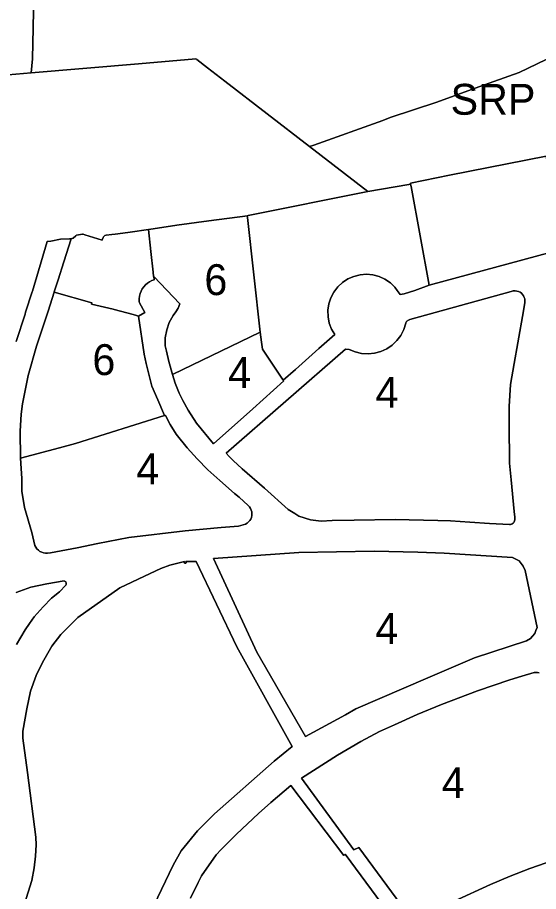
# Model space of a CAD drawing. Extents: x 598968 to 613553, y 4409678 to 4430833.
# Drawn here: x 600050.4 to 600253, y 4411856.8 to 4412196.6 of the extents above; entities that cross this region are included whole.
import ezdxf

# ---------------------------------------------------------------- set-up
doc = ezdxf.new("R2010")
doc.units = 0
for name, color, linetype in [('1', 7, 'Continuous'), ('Sòl Rústic Protegit', 7, 'Continuous'), ('Sòl Rústic Protegit - Alt Nivell de Protecció', 7, 'Continuous'), ('ZONA 4. CASES UNIFAMILIRAS AÏLLADES EN PARCEL.LES', 7, 'Continuous'), ('ZONA 6. EDIFICIS DE PISOS_ AÏLLATS I EN PARCEL.LES', 7, 'Continuous')]:
    doc.layers.add(name, color=color, linetype=linetype)

msp = doc.modelspace()

# ---------------------------------------------------------------- linework, layer by layer
at = {"layer": '1'}
for points in [[(600049.8615, 4412070.618), (600053.3133, 4412081.2583), (600053.5626, 4412082.0269), (600056.1294, 4412089.9391), (600056.2215, 4412090.2229), (600061.9315, 4412109.4578), (600063.2902, 4412109.7029), (600067.1415, 4412110.3979), (600070.5914, 4412110.4879), (600070.8652, 4412110.5224), (600071.2192, 4412110.583), (600071.4814, 4412110.6279), (600071.6514, 4412110.6779), (600071.9914, 4412110.7979), (600073.0314, 4412111.7679), (600073.3714, 4412111.9279), (600075.7014, 4412112.3879), (600075.9752, 4412112.2999), (600076.5414, 4412112.1179), (600083.2509, 4412110.0725), (600083.3313, 4412110.048), (600083.3423, 4412110.0774), (600083.3571, 4412110.1172), (600083.7027, 4412111.0448), (600083.7113, 4412111.068), (600083.8813, 4412111.358), (600084.1013, 4412111.618), (600084.3913, 4412111.808), (600084.8512, 4412111.938), (600087.0881, 4412112.2332), (600088.3143, 4412112.3949), (600091.3819, 4412112.7996), (600094.1674, 4412113.167), (600101.3929, 4412114.1197), (600101.4317, 4412114.1254), (600101.4381, 4412114.1263), (600112.2909, 4412115.9083), (600124.8032, 4412117.561), (600139.8025, 4412119.5439), (600140.1406, 4412119.5886), (600186.6101, 4412128.919), (600163.972, 4412146.4208), (600131.0638, 4412171.8626), (600124.3198, 4412177.0765), (600120.1257, 4412180.2714), (600119.9641, 4412180.3945), (600119.8028, 4412180.5173), (600097.4846, 4412178.6181), (600055.7347, 4412175.0653), (600046.7796, 4412174.3032)], [(600262.7291, 4412106.6801), (600210.4311, 4412092.5694), (600210.4227, 4412092.5669), (600204.9248, 4412090.4696), (600200.7461, 4412089.209), (600199.2349, 4412088.8495), (600198.0504, 4412090.4502), (600197.1842, 4412091.6995), (600195.3745, 4412093.4355), (600193.2995, 4412094.8438), (600191.018, 4412095.8844), (600188.5942, 4412096.5279), (600186.0969, 4412096.7562), (600183.5967, 4412096.5628), (600181.1642, 4412095.953), (600178.8682, 4412094.9443), (600176.7738, 4412093.5651), (600174.9402, 4412091.8544), (600173.4191, 4412089.8606), (600172.2537, 4412087.6401), (600171.4768, 4412085.2558), (600171.1105, 4412082.7749), (600171.1652, 4412080.2678), (600171.6392, 4412077.8052), (600172.519, 4412075.4569), (600173.7801, 4412073.2894), (600167.6182, 4412067.8515), (600158.4369, 4412059.7489), (600153.7424, 4412055.606), (600153.9602, 4412055.2793), (600141.8561, 4412044.4851), (600126.6705, 4412030.8492), (600120.0006, 4412038.919), (600116.7406, 4412043.879), (600114.6507, 4412047.6389), (600113.2907, 4412050.5589), (600111.7407, 4412054.3788), (600110.6158, 4412057.7946), (600109.2708, 4412062.8287), (600108.3108, 4412066.8687), (600107.8208, 4412068.9787), (600107.8776, 4412072.0645), (600108.4192, 4412075.1031), (600109.432, 4412078.0187), (600110.8908, 4412080.7386), (600111.9807, 4412082.1192), (600112.8792, 4412083.6313), (600113.5708, 4412085.2486), (600103.3456, 4412095.915), (600103.4795, 4412094.6664), (600102.681, 4412094.3384), (600101.771, 4412093.8884), (600100.921, 4412093.3284), (600100.161, 4412092.6684), (600099.471, 4412091.9184), (600098.891, 4412091.0784), (600098.421, 4412090.1884), (600098.061, 4412089.2384), (600097.821, 4412088.2484), (600097.721, 4412087.2384), (600097.731, 4412086.2184), (600097.891, 4412085.6484), (600099.9054, 4412081.8442), (600097.4411, 4412080.4786), (600099.6004, 4412065.6697), (600100.4364, 4412062.0667), (600102.6109, 4412053.2334), (600105.0151, 4412047.9689), (600107.5508, 4412041.869), (600107.5937, 4412041.8106), (600107.8806, 4412041.901), (600109.7807, 4412038.3089), (600112.1486, 4412034.5515), (600116.3973, 4412029.2343), (600120.2029, 4412025.0051), (600124.4505, 4412020.7192), (600129.0504, 4412016.6293), (600134.8353, 4412011.5098), (600136.5553, 4412010.0544), (600140.0902, 4412006.8145), (600140.5901, 4412006.3014), (600140.9979, 4412005.7124), (600141.3023, 4412005.0639), (600141.4948, 4412004.3738), (600141.5701, 4412003.6614), (600141.5261, 4412002.9464), (600141.3641, 4412002.2485), (600141.0884, 4412001.5873), (600140.7068, 4412000.981), (600140.2299, 4412000.4464), (600139.6709, 4411999.9985), (600139.0452, 4411999.6495), (600136.3152, 4411998.8795), (600129.5503, 4411998.3194), (600115.5713, 4411997.0609), (600093.662, 4411994.3632), (600081.6435, 4411992.0302), (600073.548, 4411990.4186), (600063.2401, 4411988.4464), (600062.053, 4411988.366), (600061.2904, 4411988.3438), (600060.5342, 4411988.4448), (600059.8041, 4411988.6665), (600059.1194, 4411989.0029), (600058.4978, 4411989.4453), (600057.9556, 4411989.9821), (600057.5071, 4411990.5992), (600057.1639, 4411991.2806), (600055.9069, 4411996.3742), (600053.0813, 4412006.1185), (600052.0613, 4412012.4485), (600052.0913, 4412017.3084), (600051.8414, 4412021.2934), (600051.5915, 4412025.2785), (600051.4391, 4412035.7522), (600051.7813, 4412042.3955), (600052.2839, 4412046.3341), (600054.4999, 4412057.3549), (600057.8123, 4412068.7686), (600062.2693, 4412082.46), (600064.6883, 4412089.8585), (600064.7053, 4412089.9109), (600066.1656, 4412094.5453), (600068.391, 4412101.6077), (600071.2192, 4412110.583), (600070.8652, 4412110.5224), (600070.5914, 4412110.4879), (600067.1415, 4412110.3979), (600063.2902, 4412109.7029), (600061.9315, 4412109.4578), (600056.2215, 4412090.2229), (600056.1294, 4412089.9391), (600053.5626, 4412082.0269), (600053.3133, 4412081.2583), (600049.8615, 4412070.618)], [(600047.3083, 4411833.433), (600055.9112, 4411861.0664), (600056.8748, 4411865.9952), (600057.4139, 4411870.4996), (600057.6244, 4411874.8692), (600057.551, 4411877.8432), (600054.2469, 4411903.0482), (600052.4267, 4411916.4206), (600052.4933, 4411919.0858), (600054.0587, 4411927.8213), (600055.4528, 4411934.6005), (600057.661, 4411940.7246), (600060.0778, 4411945.8539), (600063.7094, 4411952.1345), (600067.3009, 4411956.689), (600073.9111, 4411963.2891), (600090.1407, 4411974.8292), (600101.9189, 4411980.3707), (600106.1348, 4411982.4116), (600109.6232, 4411983.6618), (600115.3405, 4411985.0294), (600115.3, 4411984.9768), (600115.269, 4411984.9181), (600115.2483, 4411984.855), (600115.2386, 4411984.7893), (600115.2401, 4411984.7229), (600115.2529, 4411984.6577), (600115.2765, 4411984.5956), (600115.3102, 4411984.5384), (600115.3531, 4411984.4878), (600115.404, 4411984.4451), (600115.4613, 4411984.4116), (600115.5235, 4411984.3883), (600115.5886, 4411984.3758), (600115.655, 4411984.3746), (600115.7207, 4411984.3846), (600115.7837, 4411984.4055), (600115.8423, 4411984.4368), (600115.8947, 4411984.4776), (600115.9395, 4411984.5266), (600115.9754, 4411984.5825), (600116.0013, 4411984.6436), (600116.0164, 4411984.7083), (600116.0205, 4411984.7746), (600116.0133, 4411984.8406), (600115.995, 4411984.9044), (600115.9662, 4411984.9643), (600115.9277, 4411985.0184), (600115.8806, 4411985.0652), (600119.9262, 4411985.1364), (600135.6651, 4411951.8536), (600157.2382, 4411913.1078), (600150.2627, 4411907.4293), (600126.9553, 4411886.9084), (600120.4289, 4411880.3218), (600114.0378, 4411872.5894), (600110.8813, 4411867.0087), (600103.4226, 4411851.2731)], [(600049.9164, 4411973.087), (600055.5817, 4411975.1205), (600061.7464, 4411976.4456), (600068.5541, 4411977.5326), (600068.7222, 4411977.4667), (600069.1592, 4411977.1819), (600069.2996, 4411976.6876), (600069.343, 4411976.4457), (600069.3095, 4411976.147), (600069.1882, 4411975.8372), (600066.6782, 4411973.3356), (600063.6342, 4411970.7754), (600060.4189, 4411967.4243), (600056.917, 4411963.5264), (600055.1112, 4411960.9603), (600053.3454, 4411958.4509), (600049.9554, 4411952.8451)], [(600204.9496, 4411844.2805), (600183.1431, 4411873.8948), (600181.2357, 4411872.9034), (600160.801, 4411900.8292), (600174.8031, 4411909.794), (600183.9284, 4411915.0814), (600191.2021, 4411918.9549), (600196.9393, 4411921.5919), (600205.8249, 4411925.5367), (600215.2392, 4411929.4402), (600229.2993, 4411934.7638), (600241.8117, 4411939.1135), (600246.5122, 4411940.513), (600251.3232, 4411941.8849), (600252.632, 4411941.8984), (600253.1968, 4411941.7776)], [(600117.7267, 4411854.1749), (600120.7046, 4411860.3242), (600121.9615, 4411862.8214), (600127.6143, 4411870.9573), (600129.5983, 4411873.153), (600135.5, 4411879.1189), (600144.1398, 4411887.0586), (600148.9525, 4411891.3378), (600156.7362, 4411898.0025), (600177.3163, 4411870.736), (600177.7522, 4411871.2171), (600200.1233, 4411841.0695)], [(600255.9473, 4411867.8648), (600249.6677, 4411865.7518), (600241.9879, 4411862.79), (600234.2846, 4411859.4223), (600220.2119, 4411852.9536)]]:
    msp.add_lwpolyline(points, dxfattribs=at)
for points in [[(600262.813, 4412106.7175), (600261.0076, 4412116.2647), (600258.611, 4412128.9381), (600255.9993, 4412142.7497), (600218.3736, 4412135.2512), (600203.2099, 4412132.2292), (600203.2723, 4412131.8236), (600203.4318, 4412130.9483), (600210.4227, 4412092.5669), (600210.4311, 4412092.5694), (600262.7291, 4412106.6801)], [(600210.4227, 4412092.5669), (600203.4318, 4412130.9483), (600203.2723, 4412131.8236), (600202.5975, 4412131.6822), (600186.6101, 4412128.919), (600140.1406, 4412119.5886), (600139.8025, 4412119.5439), (600139.7635, 4412119.5361), (600139.8337, 4412118.8952), (600144.7204, 4412074.279), (600145.2821, 4412070.4293), (600145.2979, 4412070.3208), (600145.6803, 4412067.6991), (600153.7424, 4412055.606), (600158.4369, 4412059.7489), (600167.6182, 4412067.8515), (600173.7801, 4412073.2894), (600172.519, 4412075.4569), (600171.6392, 4412077.8052), (600171.1652, 4412080.2678), (600171.1105, 4412082.7749), (600171.4768, 4412085.2558), (600172.2537, 4412087.6401), (600173.4191, 4412089.8606), (600174.9402, 4412091.8544), (600176.7738, 4412093.5651), (600178.8682, 4412094.9443), (600181.1642, 4412095.953), (600183.5967, 4412096.5628), (600186.0969, 4412096.7562), (600188.5942, 4412096.5279), (600191.018, 4412095.8844), (600193.2995, 4412094.8438), (600195.3745, 4412093.4355), (600197.1842, 4412091.6995), (600198.0504, 4412090.4502), (600199.2349, 4412088.8495), (600200.7461, 4412089.209), (600204.9248, 4412090.4696)], [(600103.3456, 4412095.915), (600103.3402, 4412095.9206), (600103.1605, 4412097.6405), (600102.3004, 4412105.6587), (600101.3929, 4412114.1197), (600094.1674, 4412113.167), (600091.3819, 4412112.7996), (600088.3143, 4412112.3949), (600087.0881, 4412112.2332), (600084.8512, 4412111.938), (600084.3913, 4412111.808), (600084.1013, 4412111.618), (600083.8813, 4412111.358), (600083.7113, 4412111.068), (600083.7027, 4412111.0448), (600083.3571, 4412110.1172), (600083.3423, 4412110.0774), (600083.3313, 4412110.048), (600083.2509, 4412110.0725), (600076.5414, 4412112.1179), (600075.9752, 4412112.2999), (600075.7014, 4412112.3879), (600073.3714, 4412111.9279), (600073.0314, 4412111.7679), (600071.9914, 4412110.7979), (600071.6514, 4412110.6779), (600071.4814, 4412110.6279), (600071.2192, 4412110.583), (600068.391, 4412101.6077), (600066.1656, 4412094.5453), (600064.7053, 4412089.9109), (600064.6883, 4412089.8585), (600079.2813, 4412085.6283), (600079.1424, 4412085.148), (600087.6368, 4412083.1658), (600087.9808, 4412083.087), (600095.381, 4412081.1184), (600096.7261, 4412080.7006), (600097.4411, 4412080.4786), (600099.9054, 4412081.8442), (600097.891, 4412085.6484), (600097.731, 4412086.2184), (600097.721, 4412087.2384), (600097.821, 4412088.2484), (600098.061, 4412089.2384), (600098.421, 4412090.1884), (600098.891, 4412091.0784), (600099.471, 4412091.9184), (600100.161, 4412092.6684), (600100.921, 4412093.3284), (600101.771, 4412093.8884), (600102.681, 4412094.3384), (600103.4795, 4412094.6664)], [(600244.9758, 4412070.1494), (600243.5159, 4412062.0412), (600242.1185, 4412053.9679), (600241.6212, 4412045.3277), (600241.545, 4412038.542), (600241.6966, 4412023.3073), (600242.3081, 4412016.8157), (600243.4964, 4412004.5704), (600243.7503, 4412002.3635), (600243.8313, 4412002.0002), (600243.852, 4412001.6286), (600243.8119, 4412001.2585), (600243.7121, 4412000.8999), (600243.5553, 4412000.5623), (600243.3456, 4412000.2548), (600243.0886, 4411999.9855), (600242.7912, 4411999.7617), (600242.4613, 4411999.5892), (600242.1079, 4411999.4728), (600241.7401, 4411999.4155), (600233.9708, 4411999.8974), (600226.3029, 4412000.3793), (600218.8346, 4412000.8904), (600213.817, 4412001.0736), (600202.733, 4412001.3225), (600197.2228, 4412001.4189), (600181.2848, 4412001.18), (600172.7849, 4412000.9895), (600168.5409, 4412000.7516), (600164.3275, 4412001.3443), (600159.82, 4412002.6997), (600158.24, 4412003.7147), (600155.6895, 4412005.3047), (600146.4368, 4412013.6436), (600137.8203, 4412021.1694), (600134.2704, 4412024.3493), (600132.7354, 4412025.9193), (600131.4905, 4412027.1899), (600177.9876, 4412067.6722), (600179.3653, 4412067.5442), (600181.7067, 4412066.5613), (600184.1783, 4412065.9784), (600186.7121, 4412065.8116), (600189.2388, 4412066.0653), (600191.6889, 4412066.7325), (600193.9954, 4412067.795), (600196.0947, 4412069.2236), (600197.9295, 4412070.9793), (600199.4493, 4412073.0136), (600200.6125, 4412075.2709), (600201.3871, 4412077.6892), (600201.4467, 4412077.9257), (600201.5409, 4412078.1507), (600201.6676, 4412078.359), (600201.8241, 4412078.5461), (600202.0067, 4412078.7078), (600202.2115, 4412078.8403), (600202.4337, 4412078.9407), (600202.9729, 4412079.1626), (600242.3305, 4412090.1182), (600243.1873, 4412090.3243), (600243.9516, 4412090.3499), (600244.5995, 4412090.2538), (600245.2235, 4412090.0547), (600245.8073, 4412089.7577), (600246.3357, 4412089.3707), (600246.7948, 4412088.9036), (600247.1727, 4412088.3686), (600247.4595, 4412087.7797), (600247.6478, 4412087.1524), (600247.7326, 4412086.5029), (600247.7117, 4412085.8482), (600247.1272, 4412082.6035)], [(600177.9809, 4411925.4922), (600162.393, 4411917.0669), (600143.5, 4411949.78), (600126.6408, 4411986.2572), (600159.8396, 4411988.5233), (600189.0775, 4411989.0617), (600206.0775, 4411988.7351), (600216.3666, 4411988.2735), (600242.919, 4411986.6508), (600245.5237, 4411985.3732), (600247.0589, 4411983.2859), (600247.7746, 4411981.6265), (600252.4892, 4411959.4202), (600251.9923, 4411958.2657), (600251.5946, 4411957.0455), (600250.7141, 4411956.0522), (600249.8903, 4411955.1441), (600248.3849, 4411954.2076), (600228.1391, 4411947.5709), (600209.9881, 4411939.9071), (600181.8936, 4411927.7553)]]:
    msp.add_lwpolyline(points, close=True, dxfattribs=at)
at = {"layer": 'Sòl Rústic Protegit'}
msp.add_lwpolyline([(600264.2805, 4412144.3996), (600264.4423, 4412146.2714), (600264.4469, 4412146.2918), (600264.6143, 4412147.0262), (600264.6151, 4412147.0298), (600273.6467, 4412188.6296), (600273.3737, 4412188.498), (600273.4139, 4412188.6828), (600245.4135, 4412175.1828), (600229.8511, 4412169.6828), (600213.4131, 4412163.6828), (600195.3505, 4412157.6828), (600192.4319, 4412156.5056), (600165.6077, 4412146.9482), (600165.5897, 4412146.9418), (600163.972, 4412146.4208), (600186.6101, 4412128.919), (600202.5975, 4412131.6822), (600203.2723, 4412131.8236), (600203.2099, 4412132.2292), (600218.3736, 4412135.2512), (600255.9993, 4412142.7497), (600256.7779, 4412142.9048)], close=True, dxfattribs=at)
at = {"layer": 'Sòl Rústic Protegit - Alt Nivell de Protecció'}
for points in [[(600046.7796, 4412174.3032), (600055.7347, 4412175.0653), (600056.1801, 4412180.5098), (600056.4593, 4412192.5632), (600056.4911, 4412193.9802), (600056.4921, 4412194.01), (600056.7901, 4412201.6602)], [(600056.7901, 4412201.6602), (600056.4921, 4412194.01), (600056.4911, 4412193.9802), (600056.4593, 4412192.5632), (600056.1801, 4412180.5098), (600055.7347, 4412175.0653), (600097.4846, 4412178.6181), (600119.8028, 4412180.5173), (600119.9641, 4412180.3945), (600120.1257, 4412180.2714), (600124.3198, 4412177.0765), (600131.0638, 4412171.8626), (600163.972, 4412146.4208), (600165.5897, 4412146.9418), (600165.6077, 4412146.9482), (600192.4319, 4412156.5056), (600195.3505, 4412157.6828), (600213.4131, 4412163.6828), (600229.8511, 4412169.6828), (600245.4135, 4412175.1828), (600273.4139, 4412188.6828)]]:
    msp.add_lwpolyline(points, dxfattribs=at)
at = {"layer": 'ZONA 4. CASES UNIFAMILIRAS AÏLLADES EN PARCEL.LES'}
for points in [[(600244.9758, 4412070.1494), (600247.1272, 4412082.6035), (600247.7117, 4412085.8482), (600247.7326, 4412086.5029), (600247.6478, 4412087.1524), (600247.4595, 4412087.7797), (600247.1727, 4412088.3686), (600246.7948, 4412088.9036), (600246.3357, 4412089.3707), (600245.8073, 4412089.7577), (600245.2235, 4412090.0547), (600244.5995, 4412090.2538), (600243.9516, 4412090.3499), (600243.1873, 4412090.3243), (600242.3305, 4412090.1182), (600202.9729, 4412079.1626), (600202.4337, 4412078.9407), (600202.2115, 4412078.8403), (600202.0067, 4412078.7078), (600201.8241, 4412078.5461), (600201.6676, 4412078.359), (600201.5409, 4412078.1507), (600201.4467, 4412077.9257), (600201.3871, 4412077.6892), (600200.6125, 4412075.2709), (600199.4493, 4412073.0136), (600197.9295, 4412070.9793), (600196.0947, 4412069.2236), (600193.9954, 4412067.795), (600191.6889, 4412066.7325), (600189.2388, 4412066.0653), (600186.7121, 4412065.8116), (600184.1783, 4412065.9784), (600181.7067, 4412066.5613), (600179.3653, 4412067.5442), (600177.9876, 4412067.6722), (600131.4905, 4412027.1899), (600132.7354, 4412025.9193), (600134.2704, 4412024.3493), (600137.8203, 4412021.1694), (600146.4368, 4412013.6436), (600155.6895, 4412005.3047), (600158.24, 4412003.7147), (600159.82, 4412002.6997), (600164.3275, 4412001.3443), (600168.5409, 4412000.7516), (600172.7849, 4412000.9895), (600181.2848, 4412001.18), (600197.2228, 4412001.4189), (600202.733, 4412001.3225), (600213.817, 4412001.0736), (600218.8346, 4412000.8904), (600226.3029, 4412000.3793), (600233.9708, 4411999.8974), (600241.7401, 4411999.4155), (600242.1079, 4411999.4728), (600242.4613, 4411999.5892), (600242.7912, 4411999.7617), (600243.0886, 4411999.9855), (600243.3456, 4412000.2548), (600243.5553, 4412000.5623), (600243.7121, 4412000.8999), (600243.8119, 4412001.2585), (600243.852, 4412001.6286), (600243.8313, 4412002.0002), (600243.7503, 4412002.3635), (600243.4964, 4412004.5704), (600242.3081, 4412016.8157), (600241.6966, 4412023.3073), (600241.545, 4412038.542), (600241.6212, 4412045.3277), (600242.1185, 4412053.9679), (600243.5159, 4412062.0412)], [(600153.7424, 4412055.606), (600145.6803, 4412067.6991), (600145.2979, 4412070.3208), (600145.2821, 4412070.4293), (600144.7204, 4412074.279), (600110.6158, 4412057.7946), (600111.7407, 4412054.3788), (600113.2907, 4412050.5589), (600114.6507, 4412047.6389), (600116.7406, 4412043.879), (600120.0006, 4412038.919), (600126.6705, 4412030.8492), (600141.8561, 4412044.4851), (600153.9602, 4412055.2793)], [(600051.5915, 4412025.2785), (600051.8414, 4412021.2934), (600052.0913, 4412017.3084), (600052.0613, 4412012.4485), (600053.0813, 4412006.1185), (600055.9069, 4411996.3742), (600057.1639, 4411991.2806), (600057.5071, 4411990.5992), (600057.9556, 4411989.9821), (600058.4978, 4411989.4453), (600059.1194, 4411989.0029), (600059.8041, 4411988.6665), (600060.5342, 4411988.4448), (600061.2904, 4411988.3438), (600062.053, 4411988.366), (600063.2401, 4411988.4464), (600073.548, 4411990.4186), (600081.6435, 4411992.0302), (600093.662, 4411994.3632), (600115.5713, 4411997.0609), (600129.5503, 4411998.3194), (600136.3152, 4411998.8795), (600139.0452, 4411999.6495), (600139.6709, 4411999.9985), (600140.2299, 4412000.4464), (600140.7068, 4412000.981), (600141.0884, 4412001.5873), (600141.3641, 4412002.2485), (600141.5261, 4412002.9464), (600141.5701, 4412003.6614), (600141.4948, 4412004.3738), (600141.3023, 4412005.0639), (600140.9979, 4412005.7124), (600140.5901, 4412006.3014), (600140.0902, 4412006.8145), (600136.5553, 4412010.0544), (600134.8353, 4412011.5098), (600129.0504, 4412016.6293), (600124.4505, 4412020.7192), (600120.2029, 4412025.0051), (600116.3973, 4412029.2343), (600112.1486, 4412034.5515), (600109.7807, 4412038.3089), (600107.8806, 4412041.901), (600107.5937, 4412041.8106), (600072.9942, 4412030.9098), (600066.6781, 4412029.248)], [(600177.9809, 4411925.4922), (600181.8936, 4411927.7553), (600209.9881, 4411939.9071), (600228.1391, 4411947.5709), (600248.3849, 4411954.2076), (600249.8903, 4411955.1441), (600250.7141, 4411956.0522), (600251.5946, 4411957.0455), (600251.9923, 4411958.2657), (600252.4892, 4411959.4202), (600247.7746, 4411981.6265), (600247.0589, 4411983.2859), (600245.5237, 4411985.3732), (600242.919, 4411986.6508), (600216.3666, 4411988.2735), (600206.0775, 4411988.7351), (600189.0775, 4411989.0617), (600159.8396, 4411988.5233), (600126.6408, 4411986.2572), (600143.5, 4411949.78), (600162.393, 4411917.0669)]]:
    msp.add_lwpolyline(points, close=True, dxfattribs=at)
for points in [[(600103.4226, 4411851.2731), (600110.8813, 4411867.0087), (600114.0378, 4411872.5894), (600120.4289, 4411880.3218), (600126.9553, 4411886.9084), (600150.2627, 4411907.4293), (600157.2382, 4411913.1078), (600135.6651, 4411951.8536), (600119.9262, 4411985.1364), (600115.8806, 4411985.0652), (600115.9277, 4411985.0184), (600115.9662, 4411984.9643), (600115.995, 4411984.9044), (600116.0133, 4411984.8406), (600116.0205, 4411984.7746), (600116.0164, 4411984.7083), (600116.0013, 4411984.6436), (600115.9754, 4411984.5825), (600115.9395, 4411984.5266), (600115.8947, 4411984.4776), (600115.8423, 4411984.4368), (600115.7837, 4411984.4055), (600115.7207, 4411984.3846), (600115.655, 4411984.3746), (600115.5886, 4411984.3758), (600115.5235, 4411984.3883), (600115.4613, 4411984.4116), (600115.404, 4411984.4451), (600115.3531, 4411984.4878), (600115.3102, 4411984.5384), (600115.2765, 4411984.5956), (600115.2529, 4411984.6577), (600115.2401, 4411984.7229), (600115.2386, 4411984.7893), (600115.2483, 4411984.855), (600115.269, 4411984.9181), (600115.3, 4411984.9768), (600115.3405, 4411985.0294), (600109.6232, 4411983.6618), (600106.1348, 4411982.4116), (600101.9189, 4411980.3707), (600090.1407, 4411974.8292), (600073.9111, 4411963.2891), (600067.3009, 4411956.689), (600063.7094, 4411952.1345), (600060.0778, 4411945.8539), (600057.661, 4411940.7246), (600055.4528, 4411934.6005), (600054.0587, 4411927.8213), (600052.4933, 4411919.0858), (600052.4267, 4411916.4206), (600054.2469, 4411903.0482), (600057.551, 4411877.8432), (600057.6244, 4411874.8692), (600057.4139, 4411870.4996), (600056.8748, 4411865.9952), (600055.9112, 4411861.0664), (600047.3083, 4411833.433)], [(600049.9554, 4411952.8451), (600053.3454, 4411958.4509), (600055.1112, 4411960.9603), (600056.917, 4411963.5264), (600060.4189, 4411967.4243), (600063.6342, 4411970.7754), (600066.6782, 4411973.3356), (600069.1882, 4411975.8372), (600069.3095, 4411976.147), (600069.343, 4411976.4457), (600069.2996, 4411976.6876), (600069.1592, 4411977.1819), (600068.7222, 4411977.4667), (600068.5541, 4411977.5326), (600061.7464, 4411976.4456), (600055.5817, 4411975.1205), (600049.9164, 4411973.087)], [(600253.1968, 4411941.7776), (600252.632, 4411941.8984), (600251.3232, 4411941.8849), (600246.5122, 4411940.513), (600241.8117, 4411939.1135), (600229.2993, 4411934.7638), (600215.2392, 4411929.4402), (600205.8249, 4411925.5367), (600196.9393, 4411921.5919), (600191.2021, 4411918.9549), (600183.9284, 4411915.0814), (600174.8031, 4411909.794), (600160.801, 4411900.8292), (600181.2357, 4411872.9034), (600183.1431, 4411873.8948), (600204.9496, 4411844.2805)], [(600200.1233, 4411841.0695), (600177.7522, 4411871.2171), (600177.3163, 4411870.736), (600156.7362, 4411898.0025), (600148.9525, 4411891.3378), (600144.1398, 4411887.0586), (600135.5, 4411879.1189), (600129.5983, 4411873.153), (600127.6143, 4411870.9573), (600121.9615, 4411862.8214), (600120.7046, 4411860.3242), (600117.7267, 4411854.1749)], [(600220.2119, 4411852.9536), (600234.2846, 4411859.4223), (600241.9879, 4411862.79), (600249.6677, 4411865.7518), (600255.9473, 4411867.8648)]]:
    msp.add_lwpolyline(points, dxfattribs=at)
at = {"layer": 'ZONA 6. EDIFICIS DE PISOS_ AÏLLATS I EN PARCEL.LES'}
for points in [[(600144.7204, 4412074.279), (600139.8337, 4412118.8952), (600139.7635, 4412119.5361), (600139.8025, 4412119.5439), (600124.8032, 4412117.561), (600112.2909, 4412115.9083), (600101.4381, 4412114.1263), (600101.4317, 4412114.1254), (600101.3929, 4412114.1197), (600102.3004, 4412105.6587), (600103.1605, 4412097.6405), (600103.3402, 4412095.9206), (600103.3456, 4412095.915), (600113.5708, 4412085.2486), (600112.8792, 4412083.6313), (600111.9807, 4412082.1192), (600110.8908, 4412080.7386), (600109.432, 4412078.0187), (600108.4192, 4412075.1031), (600107.8776, 4412072.0645), (600107.8208, 4412068.9787), (600108.3108, 4412066.8687), (600109.2708, 4412062.8287), (600110.6158, 4412057.7946)], [(600097.4411, 4412080.4786), (600096.7261, 4412080.7006), (600095.381, 4412081.1184), (600087.9808, 4412083.087), (600087.6368, 4412083.1658), (600079.1424, 4412085.148), (600079.2813, 4412085.6283), (600064.6883, 4412089.8585), (600062.2693, 4412082.46), (600057.8123, 4412068.7686), (600054.4999, 4412057.3549), (600052.2839, 4412046.3341), (600051.7813, 4412042.3955), (600051.4391, 4412035.7522), (600051.5915, 4412025.2785), (600066.6781, 4412029.248), (600072.9942, 4412030.9098), (600107.5937, 4412041.8106), (600107.5508, 4412041.869), (600105.0151, 4412047.9689), (600102.6109, 4412053.2334), (600100.4364, 4412062.0667), (600099.6004, 4412065.6697)]]:
    msp.add_lwpolyline(points, close=True, dxfattribs=at)

# ---------------------------------------------------------------- texts
at = {"layer": 'Sòl Rústic Protegit'}
msp.add_text('SRP', height=12, dxfattribs=at).set_placement((600218.8094, 4412158.8009))
at = {"layer": 'ZONA 4. CASES UNIFAMILIRAS AÏLLADES EN PARCEL.LES'}
for p in [(600132.288, 4412052.5641), (600189.6116, 4412044.8827), (600096.5808, 4412015.1224), (600189.565, 4411953.0643), (600215.369, 4411893.0895)]:
    msp.add_text('4', height=12, dxfattribs=at).set_placement(p)
at = {"layer": 'ZONA 6. EDIFICIS DE PISOS_ AÏLLATS I EN PARCEL.LES'}
for p in [(600123.0567, 4412088.6693), (600079.5164, 4412057.5685)]:
    msp.add_text('6', height=12, dxfattribs=at).set_placement(p)

doc.saveas('drawing.dxf')
